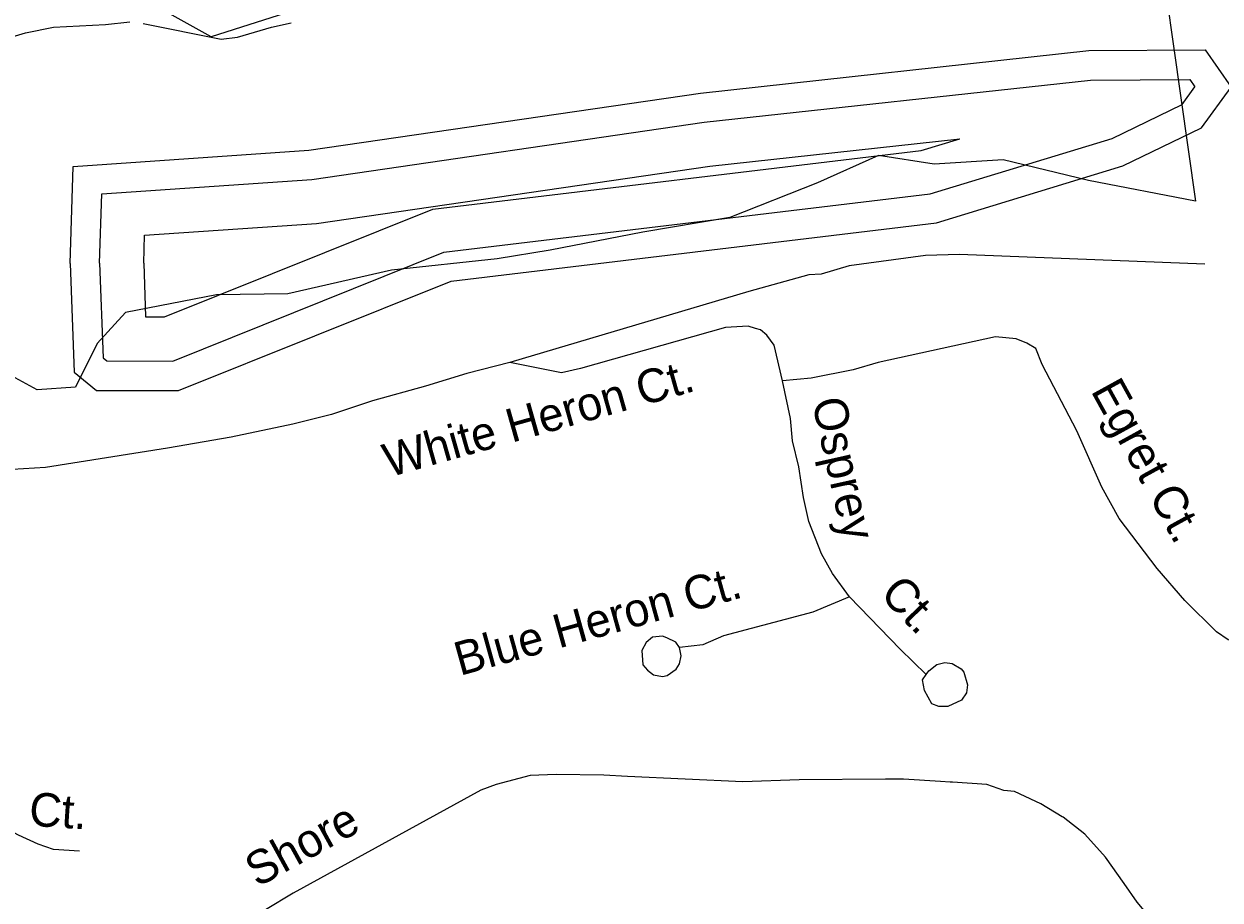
# Model space of a CAD drawing. Extents: x 2104537 to 2336408, y 34176 to 229611.
# Drawn here: x 2142926 to 2145593, y 49325 to 51279 of the extents above; entities that cross this region are included whole.
import ezdxf

# ---------------------------------------------------------------- set-up
doc = ezdxf.new("R2010")
doc.units = 0
for name, color, linetype in [('Exist Boundary Political City Limit New', 7, 'Continuous'), ('Exist Hydrographic Buffer Line', 7, 'Continuous'), ('Exist Hydrographic Lake Shore', 7, 'Continuous'), ('Exist Road Non-System Type 51', 7, 'Continuous'), ('Exist Road Non-System Type 51 Label', 7, 'Continuous'), ('Map Preparation Boundary City Limit Buffer Line', 7, 'Continuous')]:
    doc.layers.add(name, color=color, linetype=linetype)

msp = doc.modelspace()

# ---------------------------------------------------------------- linework, layer by layer
at = {"layer": 'Exist Boundary Political City Limit New'}
for points in [[(2145424.8, 51686.1), (2145539, 50883.8), (2145299.8, 50929.5), (2145109.8, 50975.9), (2144956.2, 50966.6), (2144832, 50985.7), (2144695.5, 50924.6), (2144500.2, 50847), (2144306, 50814.9), (2144099.8, 50774.3), (2143981.2, 50755.1), (2143746, 50729.7), (2143514.8, 50677.2), (2143355.5, 50674.6), (2143152.5, 50635.4), (2143089, 50566.5), (2143041.2, 50468.6), (2142955.8, 50462.5), (2142823.8, 50534.1)], [(2144010.8, 51463.4), (2143343.5, 51250.3), (2142712.5, 51601.6)]]:
    msp.add_lwpolyline(points, dxfattribs=at)
at = {"layer": 'Exist Hydrographic Buffer Line'}
for points in [[(2143094.5, 50745.2), (2143099.5, 50900), (2143567.9, 50932), (2144443.2, 51059.6), (2145304.8, 51154), (2145525.9, 51155.3), (2145537.5, 51138.8)], [(2143094.5, 50745.2), (2143102.3, 50534.4), (2143111.1, 50527.3), (2143258.2, 50527.1), (2143862.6, 50769.8), (2144947.3, 50900.1), (2145352.9, 51023.4), (2145508.6, 51099.2), (2145537.5, 51138.8)], [(2143193, 50745.4), (2143195, 50807.9), (2143578.4, 50834), (2144455.7, 50962), (2145013.1, 51023)], [(2143193, 50745.4), (2143197.4, 50625.6), (2143239.2, 50625.5), (2143837.9, 50865.9), (2144926.9, 50996.8), (2145013.1, 51023)]]:
    msp.add_lwpolyline(points, dxfattribs=at)
at = {"layer": 'Exist Hydrographic Lake Shore'}
for points in [[(2143028.9, 50745), (2143035.8, 50961.4), (2143561, 50997.3), (2144434.9, 51124.7), (2145301, 51219.6), (2145560, 51221.1), (2145618, 51138)], [(2143028.9, 50745), (2143037.9, 50502), (2143087.9, 50461.7), (2143270.8, 50461.4), (2143879, 50705.6), (2144960.9, 50835.7), (2145376.9, 50962.2), (2145552, 51047.4), (2145618, 51138)]]:
    msp.add_lwpolyline(points, dxfattribs=at)
at = {"layer": 'Exist Road Non-System Type 51'}
for p, q in [((2144991.9, 49587.7), (2144970.2, 49589)), ((2144997, 49587.4), (2144991.9, 49587.7)), ((2145148, 49561), (2145146.5, 49561.7))]:
    msp.add_line(p, q, dxfattribs=at)
for points in [[(2142780.1, 51202.6), (2142842, 51232.9), (2142929.8, 51259.4), (2142991.8, 51271.7), (2143108, 51278), (2143162, 51284.1)], [(2143191.7, 51280.3), (2143366, 51245.1), (2143402.1, 51249.3), (2143478, 51271.8), (2143521.9, 51281.8)], [(2145559.1, 50743.2), (2145012, 50764.4), (2144936.2, 50762.3), (2144766.1, 50739.3), (2144704.1, 50721.2), (2144676.2, 50719.1), (2144542.6, 50682.3), (2144009.3, 50523.9)], [(2144557.7, 50599.7), (2144540.7, 50604.6), (2144490.8, 50602.2), (2144167.2, 50510.7), (2144125, 50501.1), (2144009.3, 50523.9)], [(2144617.4, 50482.7), (2144599, 50562.7), (2144583, 50584.7), (2144568.8, 50596.5), (2144557.7, 50599.7)], [(2145973.9, 49852.7), (2145815.9, 49864), (2145739.8, 49877.9), (2145692, 49883.4), (2145611.7, 49905.3), (2145585.8, 49923.2), (2145515.2, 49992.8), (2145453, 50064.6), (2145368.5, 50176.1), (2145330.1, 50245.8), (2145273.8, 50371.5), (2145197, 50519.4), (2145182.9, 50555.4), (2145162.8, 50567.3), (2145138.7, 50576.9), (2145092.8, 50580.8), (2144831.2, 50523.8), (2144775.1, 50507.5), (2144681.2, 50489), (2144617.4, 50482.7)], [(2144009.3, 50523.9), (2143913.3, 50499.5), (2143821.5, 50471.1), (2143703.4, 50438.6), (2143611.6, 50408.2), (2143525.9, 50385.9), (2143387.9, 50357.4), (2143246, 50332.6), (2142974.1, 50289.6), (2142900.2, 50285.1), (2142846.5, 50273.1), (2142790.4, 50272.8)], [(2144767.3, 50001.4), (2144729.2, 50053.3), (2144704.8, 50097.1), (2144676.7, 50169.1), (2144664.3, 50222.9), (2144654.1, 50291), (2144639.8, 50349), (2144635.5, 50399), (2144617.4, 50482.7)], [(2144767.3, 50001.4), (2144685.6, 49967.2), (2144485.7, 49914.3), (2144440.1, 49894.1), (2144388.1, 49887.9)], [(2144938.2, 49828.1), (2144879.9, 49884), (2144767.3, 50001.4)], [(2144388.1, 49887.9), (2144379.8, 49899.9), (2144360, 49909.8), (2144349.9, 49913.6), (2144327.8, 49911.4), (2144313.8, 49899.5), (2144304, 49881.4), (2144306, 49849.5), (2144316.2, 49837.5), (2144330.2, 49827.4), (2144350.1, 49823.7), (2144360.3, 49825.8), (2144380.3, 49839.8), (2144388.1, 49851.8), (2144392, 49869.8), (2144388.1, 49887.9)], [(2144938.2, 49828.1), (2144944.2, 49836.2), (2144961.9, 49850.3), (2144980, 49854.5), (2144996.1, 49852.6), (2145016.2, 49840.7), (2145022.3, 49832.7), (2145030.3, 49804.7), (2145028.3, 49786.7), (2145016.5, 49770.5), (2144986.3, 49756.3), (2144966.3, 49756.3), (2144950.4, 49762.2), (2144934.2, 49792.1), (2144930.1, 49816.1), (2144938.2, 49828.1)], [(2143050.1, 49434.1), (2142992.1, 49437.8), (2142957.9, 49449.6), (2142914, 49469.2), (2142873.7, 49491.3), (2142843.6, 49514.8), (2142777.4, 49586.6), (2142739.1, 49640.5), (2142700.8, 49714.5), (2142686.7, 49732.1), (2142668.7, 49748.2), (2142660.7, 49762.1), (2142644.6, 49773.9), (2142604.7, 49781.9)], [(2144271.7, 49600.6), (2144219.2, 49603.1), (2144113.2, 49604.5), (2144055.1, 49602.3), (2143979.3, 49582.1), (2143945.2, 49570), (2143526.4, 49339.9), (2143402.9, 49265.5), (2143334.9, 49229.1), (2143261.1, 49194.7), (2143189.1, 49190.5), (2143065.1, 49224.1), (2142926.9, 49257.3), (2142828.7, 49287.1), (2142488.2, 49373.4)], [(2144847.2, 49594), (2144655.1, 49593), (2144529.3, 49588.3), (2144271.7, 49600.6)], [(2144970.2, 49589), (2144887.1, 49594.1), (2144847.2, 49594)], [(2145146.5, 49561.7), (2145135.3, 49567), (2145111.3, 49569.1), (2145073.2, 49582.7), (2144997, 49587.4)], [(2145241.5, 49510.7), (2145193.5, 49539.3), (2145148, 49561)], [(2145379.4, 49361.3), (2145337.8, 49420.1), (2145291.6, 49471.8), (2145243.4, 49509.5), (2145241.5, 49510.7)], [(2145431.9, 49292.8), (2145408.4, 49320.3), (2145379.4, 49361.3)]]:
    msp.add_lwpolyline(points, dxfattribs=at)
at = {"layer": 'Map Preparation Boundary City Limit Buffer Line'}
for points in [[(2145424.8, 51686.1), (2145539, 50883.8), (2145299.8, 50929.5), (2145109.8, 50975.9), (2144956.2, 50966.6), (2144832, 50985.7), (2144695.5, 50924.6), (2144500.2, 50847), (2144306, 50814.9), (2144099.8, 50774.3), (2143981.2, 50755.1), (2143746, 50729.7), (2143514.8, 50677.2), (2143355.5, 50674.6), (2143152.5, 50635.4), (2143089, 50566.5), (2143041.2, 50468.6), (2142955.8, 50462.5), (2142823.8, 50534.1)], [(2144010.8, 51463.4), (2143343.5, 51250.3), (2142712.5, 51601.6)]]:
    msp.add_lwpolyline(points, dxfattribs=at)

# ---------------------------------------------------------------- texts
at = {"layer": 'Exist Road Non-System Type 51 Label'}
for s, rotation, p in [('White Heron Ct.', 15.7915, (2143740, 50267.2)), ('Egret Ct.', 298.8431, (2145304, 50460.9)), ('Osprey', 282.6126, (2144682.8, 50437.6)), ('Blue Heron Ct.', 15.5396, (2143898.2, 49824.5)), ('Ct.', 313.8114, (2144832.2, 50004.8)), ('Ct.', 356.3075, (2142936, 49490.7)), ('Shore', 28.7853, (2143446.2, 49352))]:
    msp.add_text(s, height=75, rotation=rotation, dxfattribs=at).set_placement(p)

doc.saveas('drawing.dxf')
